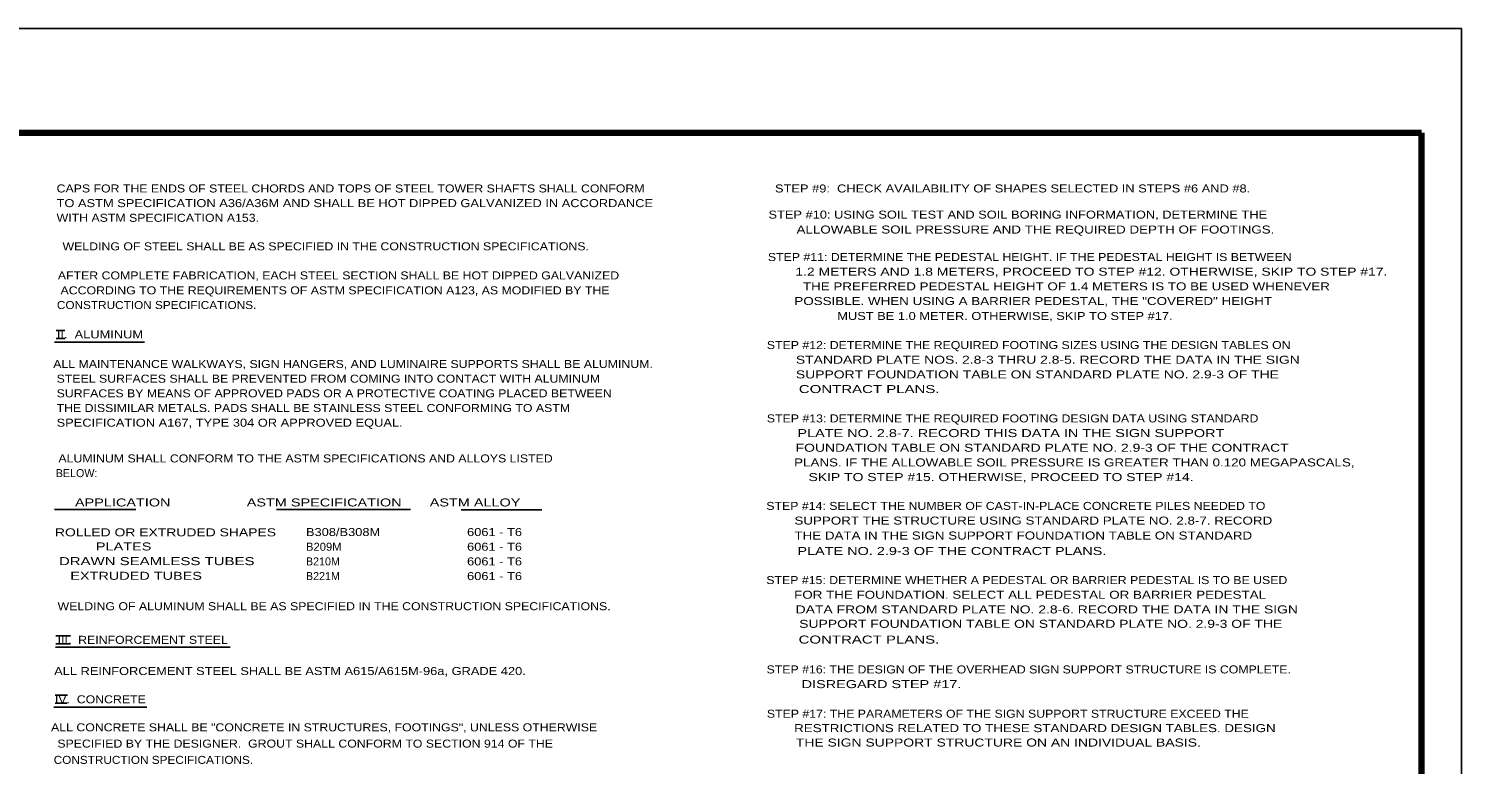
# Model space of a CAD drawing. Extents: x 312601.858 to 312602.699, y 144420.109 to 144420.704.
# Drawn here: x 312602.162 to 312602.699, y 144420.428 to 144420.704 of the extents above; entities that cross this region are included whole.
import ezdxf
from ezdxf.enums import TextEntityAlignment as Align

# ---------------------------------------------------------------- set-up
doc = ezdxf.new("R2010")
doc.units = 0
doc.header["$LTSCALE"] = 0.0012
for name, color, linetype, lineweight in [('1', 7, 'Continuous', 13), ('2', 7, 'Continuous', 25), ('39', 7, 'Continuous', 25)]:
    doc.layers.add(name, color=color, linetype=linetype, lineweight=lineweight)

msp = doc.modelspace()

# ---------------------------------------------------------------- linework, layer by layer
at = {"layer": '2'}
for p, q in [((312602.1719, 144420.5904), (312602.1752, 144420.5904)), ((312602.1713, 144420.586), (312602.2051, 144420.586)), ((312602.1719, 144420.5874), (312602.1752, 144420.5874)), ((312602.1713, 144420.5232), (312602.2018, 144420.5232)), ((312602.2546, 144420.5232), (312602.3048, 144420.5232)), ((312602.3238, 144420.5231), (312602.354, 144420.5231)), ((312602.1717, 144420.4716), (312602.2372, 144420.4716)), ((312602.1718, 144420.4759), (312602.1773, 144420.4759)), ((312602.1718, 144420.4729), (312602.1773, 144420.4729)), ((312602.1715, 144420.4536), (312602.1762, 144420.4536)), ((312602.1715, 144420.4506), (312602.1761, 144420.4506)), ((312602.175, 144420.4506), (312602.176, 144420.4506)), ((312602.1711, 144420.4492), (312602.2059, 144420.4492))]:
    msp.add_line(p, q, dxfattribs=at)
at = {"layer": '39'}
for p, q in [((312601.8578, 144420.7035), (312602.6988, 144420.7035)), ((312602.6988, 144420.1095), (312602.6988, 144420.7035)), ((312602.5735, 144420.6645), (312602.6838, 144420.6645)), ((312602.5735, 144420.6645), (312602.6838, 144420.6645)), ((312602.6838, 144420.6514), (312602.6838, 144420.6645))]:
    msp.add_line(p, q, dxfattribs=at)
at = {"layer": '39', "lineweight": 158}
for p in [(312601.9088, 144420.6645), (312602.6838, 144420.1247)]:
    msp.add_line(p, (312602.6838, 144420.6645), dxfattribs=at)

# ---------------------------------------------------------------- texts
at = {"layer": '1'}
for s, width, p in [('B308/B308M', 1.2, (312602.2656, 144420.5133)), ('6061 - T6', 1.2, (312602.326, 144420.5133)), ('B209M', 1.05, (312602.2656, 144420.5078)), ('6061 - T6', 1.2, (312602.326, 144420.5078)), ('6061 - T6', 1.2, (312602.326, 144420.5023)), ('6061 - T6', 1.2, (312602.326, 144420.4968))]:
    msp.add_text(s, height=0.003, dxfattribs=dict(at, width=width)).set_placement(p)
for s, p in [('B210M', (312602.2656, 144420.5023)), ('B221M', (312602.2656, 144420.4968))]:
    msp.add_text(s, height=0.003, dxfattribs=at).set_placement(p)
at = {"layer": '2'}
for s, width, p in [('CAPS FOR THE ENDS OF STEEL CHORDS AND TOPS OF STEEL TOWER SHAFTS SHALL CONFORM', 1.15, (312602.1721, 144420.6421)), ('TO ASTM SPECIFICATION A36/A36M AND SHALL BE HOT DIPPED GALVANIZED IN ACCORDANCE ', 1.2, (312602.1721, 144420.6366)), ('WITH ASTM SPECIFICATION A153.', 1.15, (312602.1721, 144420.6311)), ('STEP #10: USING SOIL TEST AND SOIL BORING INFORMATION, DETERMINE THE', 1.2, (312602.439, 144420.6323)), ('          ALLOWABLE SOIL PRESSURE AND THE REQUIRED DEPTH OF FOOTINGS.', 1.25, (312602.4356, 144420.6267)), ('STEP #11: DETERMINE THE PEDESTAL HEIGHT. IF THE PEDESTAL HEIGHT IS BETWEEN', 1.15, (312602.4388, 144420.6164)), ('          1.2 METERS AND 1.8 METERS, PROCEED TO STEP #12. OTHERWISE, SKIP TO STEP #17. ', 1.3, (312602.4346, 144420.6109)), ('        THE PREFERRED PEDESTAL HEIGHT OF 1.4 METERS IS TO BE USED WHENEVER ', 1.25, (312602.4408, 144420.6054)), ('          POSSIBLE. WHEN USING A BARRIER PEDESTAL, THE "COVERED" HEIGHT', 1.25, (312602.4348, 144420.5999)), ('MUST BE 1.0 METER. OTHERWISE, SKIP TO STEP #17.', 1.2, (312602.4648, 144420.5943)), ('STEP #12: DETERMINE THE REQUIRED FOOTING SIZES USING THE DESIGN TABLES ON', 1.15, (312602.4384, 144420.5834)), ('          STANDARD PLATE NOS. 2.8-3 THRU 2.8-5. RECORD THE DATA IN THE SIGN', 1.3, (312602.4348, 144420.5779)), ('STEEL SURFACES SHALL BE PREVENTED FROM COMING INTO CONTACT WITH ALUMINUM', 1.15, (312602.1721, 144420.5708)), ('          SUPPORT FOUNDATION TABLE ON STANDARD PLATE NO. 2.9-3 OF THE', 1.3, (312602.4348, 144420.5724)), ('SURFACES BY MEANS OF APPROVED PADS OR A PROTECTIVE COATING PLACED BETWEEN', 1.15, (312602.1721, 144420.5653)), ('          CONTRACT PLANS.', 1.4, (312602.4348, 144420.5669)), ('THE DISSIMILAR METALS. PADS SHALL BE STAINLESS STEEL CONFORMING TO ASTM', 1.15, (312602.1721, 144420.5598)), ('SPECIFICATION A167, TYPE 304 OR APPROVED EQUAL.', 1.2, (312602.1721, 144420.5543)), ('STEP #13: DETERMINE THE REQUIRED FOOTING DESIGN DATA USING STANDARD', 1.15, (312602.4384, 144420.5559)), ('          PLATE NO. 2.8-7. RECORD THIS DATA IN THE SIGN SUPPORT', 1.35, (312602.4348, 144420.5504)), ('          FOUNDATION TABLE ON STANDARD PLATE NO. 2.9-3 OF THE CONTRACT', 1.3, (312602.4347, 144420.5449)), ('          PLANS. IF THE ALLOWABLE SOIL PRESSURE IS GREATER THAN 0.120 MEGAPASCALS,', 1.25, (312602.4347, 144420.5394)), ('       SKIP TO STEP #15. OTHERWISE, PROCEED TO STEP #14.', 1.3, (312602.4439, 144420.5339)), ('STEP #14: SELECT THE NUMBER OF CAST-IN-PLACE CONCRETE PILES NEEDED TO', 1.15, (312602.4382, 144420.5231)), ('          SUPPORT THE STRUCTURE USING STANDARD PLATE NO. 2.8-7. RECORD', 1.25, (312602.4348, 144420.5176)), ('          THE DATA IN THE SIGN SUPPORT FOUNDATION TABLE ON STANDARD', 1.25, (312602.4348, 144420.512)), ('          PLATE NO. 2.9-3 OF THE CONTRACT PLANS.', 1.35, (312602.4348, 144420.5062)), ('STEP #15: DETERMINE WHETHER A PEDESTAL OR BARRIER PEDESTAL IS TO BE USED', 1.15, (312602.4382, 144420.4953)), ('          FOR THE FOUNDATION. SELECT ALL PEDESTAL OR BARRIER PEDESTAL', 1.25, (312602.4347, 144420.4898)), ('          DATA FROM STANDARD PLATE NO. 2.8-6. RECORD THE DATA IN THE SIGN', 1.3, (312602.4347, 144420.4843)), ('         SUPPORT FOUNDATION TABLE ON STANDARD PLATE NO. 2.9-3 OF THE ', 1.3, (312602.4375, 144420.4789)), ('          CONTRACT PLANS.', 1.4, (312602.4347, 144420.473)), ('STEP #16: THE DESIGN OF THE OVERHEAD SIGN SUPPORT STRUCTURE IS COMPLETE. ', 1.15, (312602.4383, 144420.4618)), ('         DISREGARD STEP #17.', 1.35, (312602.4379, 144420.4563)), ('STEP #17: THE PARAMETERS OF THE SIGN SUPPORT STRUCTURE EXCEED THE', 1.15, (312602.4384, 144420.4452)), ('          RESTRICTIONS RELATED TO THESE STANDARD DESIGN TABLES. DESIGN', 1.25, (312602.4347, 144420.4398)), ('          THE SIGN SUPPORT STRUCTURE ON AN INDIVIDUAL BASIS.', 1.3, (312602.4348, 144420.4344))]:
    msp.add_text(s, height=0.003, dxfattribs=dict(at, width=width)).set_placement(p)
for s, width, p in [('STEP #9:  CHECK AVAILABILITY OF SHAPES SELECTED IN STEPS #6 AND #8.', 1.2, (312602.53055, 144420.6421)), ('WELDING OF STEEL SHALL BE AS SPECIFIED IN THE CONSTRUCTION SPECIFICATIONS. ', 1.15, (312602.27365, 144420.6204)), ('AFTER COMPLETE FABRICATION, EACH STEEL SECTION SHALL BE HOT DIPPED GALVANIZED', 1.15, (312602.2778, 144420.6095)), ('ACCORDING TO THE REQUIREMENTS OF ASTM SPECIFICATION A123, AS MODIFIED BY THE', 1.15, (312602.2765, 144420.6039)), ('CONSTRUCTION SPECIFICATIONS.', 1.1, (312602.2096, 144420.5984)), ('II.  ALUMINUM', 1.2, (312602.18835, 144420.5874)), ('ALL MAINTENANCE WALKWAYS, SIGN HANGERS, AND LUMINAIRE SUPPORTS SHALL BE ALUMINUM.', 1.15, (312602.28325, 144420.5763)), ('ALUMINUM SHALL CONFORM TO THE ASTM SPECIFICATIONS AND ALLOYS LISTED', 1.15, (312602.26545, 144420.5409)), ('APPLICATION                   ASTM SPECIFICATION       ASTM ALLOY', 1.35, (312602.2625, 144420.5244)), ('APPLICATION                   ASTM SPECIFICATION       ASTM ALLOY', 1.35, (312602.2625, 144420.5244)), ('APPLICATION                   ASTM SPECIFICATION       ASTM ALLOY', 1.35, (312602.2625, 144420.5244)), ('ROLLED OR EXTRUDED SHAPES         ', 1.3, (312602.21945, 144420.5132)), ('PLATES                          ', 1.35, (312602.2168, 144420.5079)), ('DRAWN SEAMLESS TUBES               ', 1.4, (312602.22135, 144420.5024)), ('EXTRUDED TUBES                ', 1.35, (312602.21395, 144420.4969)), ('WELDING OF ALUMINUM SHALL BE AS SPECIFIED IN THE CONSTRUCTION SPECIFICATIONS.', 1.15, (312602.27615, 144420.4855)), ('III.  REINFORCEMENT STEEL', 1.15, (312602.2044, 144420.4729)), ('ALL REINFORCEMENT STEEL SHALL BE ASTM A615/A615M-96a, GRADE 420.', 1.2, (312602.2596, 144420.4612)), ('IV.  CONCRETE', 1.15, (312602.1885, 144420.4506)), ('ALL CONCRETE SHALL BE "CONCRETE IN STRUCTURES, FOOTINGS", UNLESS OTHERWISE', 1.15, (312602.2724, 144420.4401)), ('SPECIFIED BY THE DESIGNER.  GROUT SHALL CONFORM TO SECTION 914 OF THE', 1.15, (312602.2653, 144420.434)), ('CONSTRUCTION SPECIFICATIONS.', 1.1, (312602.2084, 144420.4279))]:
    msp.add_text(s, height=0.003, dxfattribs=dict(at, width=width)).set_placement(p, align=Align.CENTER)
msp.add_text('BELOW:', height=0.003, dxfattribs=at).set_placement((312602.1796, 144420.5354), align=Align.CENTER)

doc.saveas('drawing.dxf')
